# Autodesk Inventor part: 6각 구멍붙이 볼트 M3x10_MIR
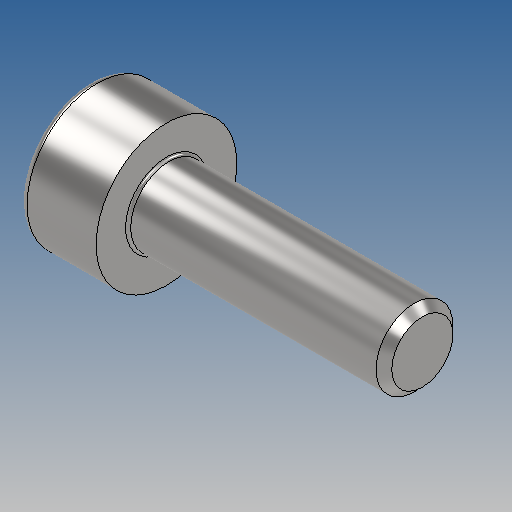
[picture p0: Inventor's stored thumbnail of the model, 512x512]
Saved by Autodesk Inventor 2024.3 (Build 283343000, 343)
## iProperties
Created: 2025-06
Part Number: 6각 구멍붙이 볼트 M3x10_MIR
Material: 강철, 연강
Description: 6각머리 태핑 나사
Document SubType Name: Modeling
Designer: user
Density: 7.85 g/cm^3
Appearance: 기본값
Author: jhkim
Sending System: Autodesk Inventor 2026
Preprocessor: ST-DEVELOPER v20.1
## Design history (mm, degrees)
derived "6각 구멍붙이 볼트 M3x10.ipt"
feature "솔리드1::6각 구멍붙이 볼트 M3x10.ipt" dims "d0" = 10
tag "피쳐 태그1"
node "솔리드1"
